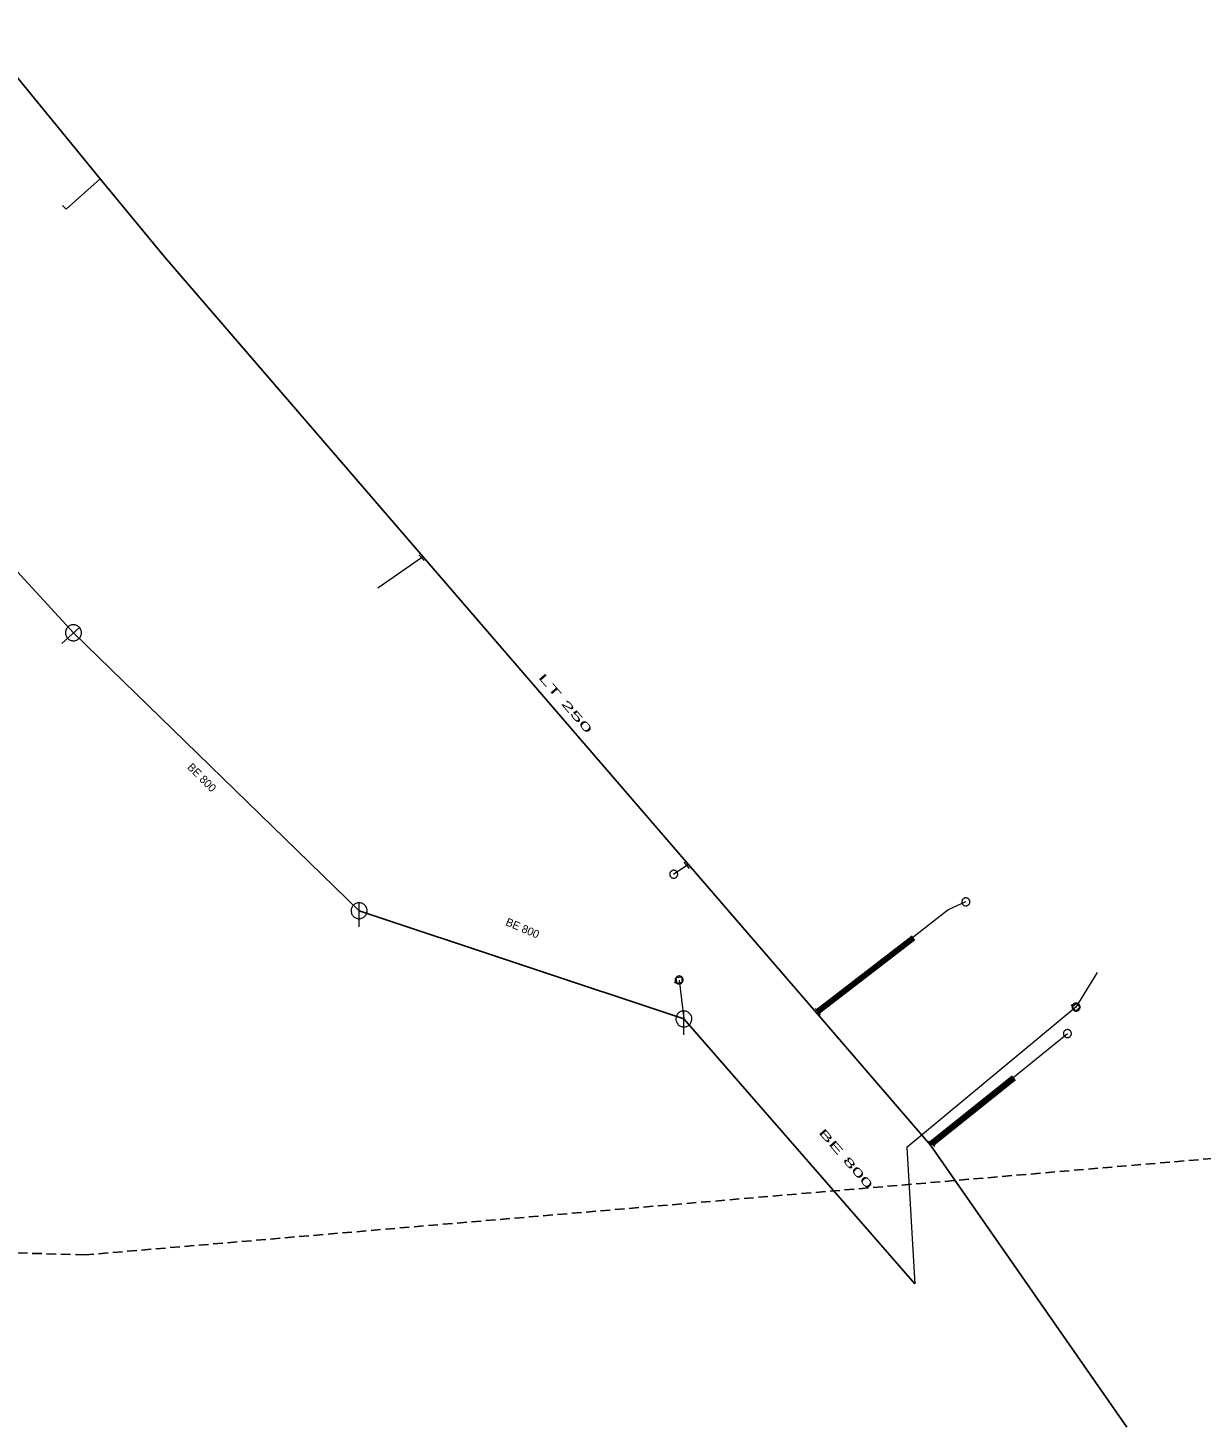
# Model space of a CAD drawing. Extents: x -807203 to -805207, y -993656 to -992505.
# Drawn here: x -805804.7 to -805658.1, y -993617.7 to -993442.8 of the extents above; entities that cross this region are included whole.
import ezdxf

# ---------------------------------------------------------------- set-up
doc = ezdxf.new("R2010")
doc.units = 0
doc.header["$LTSCALE"] = 0.4
doc.header["$PDMODE"] = 32
doc.header["$PDSIZE"] = 0.2
doc.linetypes.add('MEDIUM_DASHED', pattern=[4.5, 3, -1.5])
for name, color, linetype, lineweight in [('1', 7, 'Continuous', 13), ('11', 7, 'Continuous', 13), ('13', 7, 'Continuous', 13), ('14', 7, 'Continuous', 25), ('17', 7, 'Continuous', 25), ('22', 7, 'Continuous', 13), ('23', 7, 'Continuous', 13), ('3', 7, 'Continuous', 106), ('34', 7, 'Continuous', 13), ('63', 7, 'MEDIUM_DASHED', 25)]:
    doc.layers.add(name, color=color, linetype=linetype, lineweight=lineweight)

msp = doc.modelspace()

# ---------------------------------------------------------------- linework, layer by layer
at = {"layer": '11'}
for p, q in [((-805723.33, -993561.836), (-805722.73, -993566.67)), ((-805671.081, -993560.878), (-805673.723, -993565.2))]:
    msp.add_line(p, q, dxfattribs=at)
msp.add_lwpolyline([(-805673.723, -993565.2), (-805694.854, -993582.729), (-805693.85, -993599.78)], dxfattribs=at)
at = {"layer": '13'}
for p, q in [((-805755.528, -993509.035), (-805761.003, -993512.821)), ((-805722.359, -993547.474), (-805724.007, -993548.622)), ((-805691.744, -993582.248), (-805674.78, -993568.475)), ((-805691.895, -993582.435), (-805691.744, -993582.248))]:
    msp.add_line(p, q, dxfattribs=at)
for points in [[(-805795.712, -993461.665), (-805796.45, -993462.339), (-805799.933, -993465.458), (-805800.42, -993464.977)], [(-805705.993, -993565.763), (-805689.715, -993553.05), (-805687.47, -993552.011)]]:
    msp.add_lwpolyline(points, dxfattribs=at)
at = {"layer": '14', "lineweight": 13}
for p, q in [((-805755.36, -993508.868), (-805755.528, -993509.035)), ((-805722.18, -993547.329), (-805722.359, -993547.474)), ((-805706.16, -993565.899), (-805705.993, -993565.763))]:
    msp.add_line(p, q, dxfattribs=at)
at = {"layer": '14'}
for p, q in [((-805799.036, -993518.404), (-805763.329, -993553.149)), ((-805763.329, -993553.149), (-805722.73, -993566.67)), ((-805722.73, -993566.67), (-805693.85, -993599.78))]:
    msp.add_line(p, q, dxfattribs=at)
msp.add_lwpolyline([(-805843.754, -993470.162), (-805838.469, -993475.18), (-805826.754, -993488.287), (-805799.036, -993518.404)], dxfattribs=at)
at = {"layer": '17'}
msp.add_lwpolyline([(-805810.637, -993445.063), (-805806.327, -993448.671), (-805795.712, -993461.664), (-805787.671, -993471.416), (-805755.36, -993508.868), (-805722.18, -993547.329), (-805706.16, -993565.899), (-805691.895, -993582.435), (-805667.369, -993617.68)], dxfattribs=at)
at = {"layer": '22'}
for p, q in [((-805800.507, -993519.759), (-805798.3, -993517.726)), ((-805763.329, -993555.149), (-805763.328, -993552.149)), ((-805722.73, -993568.67), (-805722.729, -993565.67))]:
    msp.add_line(p, q, dxfattribs=at)
for points in [[(-805798.358, -993519.139), (-805798.282, -993519.061), (-805798.215, -993518.975), (-805798.157, -993518.881), (-805798.11, -993518.783), (-805798.074, -993518.679), (-805798.05, -993518.573), (-805798.038, -993518.463), (-805798.037, -993518.354), (-805798.048, -993518.245), (-805798.072, -993518.139), (-805798.106, -993518.034), (-805798.153, -993517.935), (-805798.209, -993517.841), (-805798.276, -993517.754), (-805798.352, -993517.675), (-805798.435, -993517.605), (-805798.526, -993517.543), (-805798.623, -993517.492), (-805798.726, -993517.453), (-805798.831, -993517.425), (-805798.94, -993517.409), (-805799.049, -993517.404), (-805799.159, -993517.412), (-805799.266, -993517.43), (-805799.371, -993517.462), (-805799.472, -993517.504), (-805799.568, -993517.557), (-805799.657, -993517.62), (-805799.739, -993517.693), (-805799.813, -993517.775), (-805799.877, -993517.863), (-805799.93, -993517.958), (-805799.974, -993518.058), (-805800.007, -993518.163), (-805800.027, -993518.271), (-805800.036, -993518.38), (-805800.032, -993518.49), (-805800.017, -993518.598), (-805799.99, -993518.704), (-805799.951, -993518.806), (-805799.902, -993518.904), (-805799.842, -993518.996), (-805799.772, -993519.081), (-805799.694, -993519.157), (-805799.607, -993519.224), (-805799.515, -993519.281), (-805799.416, -993519.329), (-805799.312, -993519.365), (-805799.205, -993519.389), (-805799.097, -993519.402), (-805798.987, -993519.403), (-805798.878, -993519.391), (-805798.771, -993519.369), (-805798.668, -993519.333), (-805798.568, -993519.288), (-805798.474, -993519.231), (-805798.387, -993519.164)], [(-805762.329, -993553.149), (-805762.334, -993553.04), (-805762.352, -993552.932), (-805762.382, -993552.826), (-805762.422, -993552.725), (-805762.474, -993552.628), (-805762.536, -993552.538), (-805762.608, -993552.455), (-805762.688, -993552.381), (-805762.776, -993552.315), (-805762.87, -993552.26), (-805762.97, -993552.215), (-805763.075, -993552.182), (-805763.182, -993552.16), (-805763.291, -993552.15), (-805763.401, -993552.152), (-805763.509, -993552.166), (-805763.616, -993552.191), (-805763.719, -993552.228), (-805763.817, -993552.277), (-805763.909, -993552.335), (-805763.995, -993552.404), (-805764.072, -993552.481), (-805764.141, -993552.567), (-805764.2, -993552.659), (-805764.248, -993552.757), (-805764.285, -993552.86), (-805764.311, -993552.967), (-805764.325, -993553.075), (-805764.328, -993553.185), (-805764.318, -993553.294), (-805764.297, -993553.401), (-805764.263, -993553.505), (-805764.219, -993553.605), (-805764.164, -993553.7), (-805764.098, -993553.788), (-805764.024, -993553.868), (-805763.941, -993553.94), (-805763.851, -993554.002), (-805763.755, -993554.054), (-805763.653, -993554.095), (-805763.548, -993554.125), (-805763.44, -993554.143), (-805763.33, -993554.149), (-805763.221, -993554.143), (-805763.113, -993554.125), (-805763.008, -993554.096), (-805762.906, -993554.055), (-805762.809, -993554.003), (-805762.719, -993553.941), (-805762.636, -993553.87), (-805762.561, -993553.79), (-805762.496, -993553.702), (-805762.44, -993553.608), (-805762.396, -993553.508), (-805762.362, -993553.404), (-805762.34, -993553.296), (-805762.33, -993553.187)], [(-805723.263, -993562.3), (-805723.212, -993562.291), (-805723.16, -993562.275), (-805723.112, -993562.256), (-805723.066, -993562.232), (-805723.023, -993562.203), (-805722.982, -993562.167), (-805722.947, -993562.131), (-805722.916, -993562.088), (-805722.887, -993562.045), (-805722.863, -993561.998), (-805722.845, -993561.948), (-805722.835, -993561.898), (-805722.826, -993561.846), (-805722.824, -993561.793), (-805722.83, -993561.742), (-805722.838, -993561.691), (-805722.854, -993561.639), (-805722.873, -993561.59), (-805722.897, -993561.545), (-805722.927, -993561.502), (-805722.961, -993561.462), (-805722.998, -993561.425), (-805723.04, -993561.393), (-805723.083, -993561.366), (-805723.13, -993561.343), (-805723.181, -993561.325), (-805723.231, -993561.312), (-805723.282, -993561.305), (-805723.335, -993561.305), (-805723.386, -993561.308), (-805723.438, -993561.318), (-805723.489, -993561.332), (-805723.538, -993561.351), (-805723.584, -993561.376), (-805723.626, -993561.406), (-805723.667, -993561.439), (-805723.703, -993561.477), (-805723.735, -993561.518), (-805723.763, -993561.563), (-805723.786, -993561.609), (-805723.803, -993561.66), (-805723.816, -993561.71), (-805723.824, -993561.762), (-805723.824, -993561.814), (-805723.821, -993561.865), (-805723.812, -993561.917), (-805723.796, -993561.968), (-805723.778, -993562.016), (-805723.752, -993562.062), (-805723.723, -993562.106), (-805723.689, -993562.146), (-805723.653, -993562.182), (-805723.611, -993562.213), (-805723.567, -993562.242), (-805723.519, -993562.265), (-805723.469, -993562.283), (-805723.42, -993562.295), (-805723.368, -993562.303), (-805723.314, -993562.304)], [(-805723.021, -993561.413), (-805722.932, -993562.116), (-805723.621, -993562.202), (-805723.708, -993561.499)], [(-805674.078, -993565.505), (-805674.043, -993565.544), (-805674.002, -993565.579), (-805673.96, -993565.609), (-805673.915, -993565.635), (-805673.867, -993565.655), (-805673.815, -993565.671), (-805673.765, -993565.681), (-805673.713, -993565.684), (-805673.661, -993565.686), (-805673.609, -993565.68), (-805673.556, -993565.668), (-805673.508, -993565.65), (-805673.46, -993565.63), (-805673.415, -993565.602), (-805673.375, -993565.57), (-805673.336, -993565.536), (-805673.301, -993565.495), (-805673.27, -993565.452), (-805673.244, -993565.408), (-805673.225, -993565.359), (-805673.21, -993565.309), (-805673.199, -993565.258), (-805673.194, -993565.205), (-805673.194, -993565.154), (-805673.2, -993565.102), (-805673.213, -993565.05), (-805673.229, -993565.001), (-805673.25, -993564.953), (-805673.279, -993564.909), (-805673.309, -993564.868), (-805673.345, -993564.83), (-805673.385, -993564.794), (-805673.426, -993564.762), (-805673.472, -993564.738), (-805673.52, -993564.718), (-805673.571, -993564.701), (-805673.622, -993564.692), (-805673.674, -993564.687), (-805673.726, -993564.687), (-805673.778, -993564.693), (-805673.83, -993564.706), (-805673.879, -993564.722), (-805673.927, -993564.743), (-805673.971, -993564.771), (-805674.012, -993564.801), (-805674.051, -993564.837), (-805674.086, -993564.878), (-805674.116, -993564.919), (-805674.141, -993564.966), (-805674.162, -993565.014), (-805674.178, -993565.064), (-805674.189, -993565.114), (-805674.192, -993565.166), (-805674.193, -993565.219), (-805674.187, -993565.271), (-805674.175, -993565.323), (-805674.159, -993565.371), (-805674.137, -993565.419), (-805674.109, -993565.465)], [(-805673.2, -993565.232), (-805673.745, -993565.685), (-805674.189, -993565.151), (-805673.643, -993564.699)], [(-805721.73, -993566.67), (-805721.735, -993566.561), (-805721.753, -993566.453), (-805721.783, -993566.347), (-805721.823, -993566.246), (-805721.875, -993566.149), (-805721.937, -993566.059), (-805722.009, -993565.976), (-805722.089, -993565.902), (-805722.177, -993565.836), (-805722.271, -993565.781), (-805722.371, -993565.736), (-805722.476, -993565.703), (-805722.583, -993565.681), (-805722.692, -993565.671), (-805722.802, -993565.673), (-805722.91, -993565.687), (-805723.017, -993565.712), (-805723.12, -993565.749), (-805723.218, -993565.798), (-805723.31, -993565.856), (-805723.396, -993565.925), (-805723.473, -993566.002), (-805723.542, -993566.088), (-805723.601, -993566.18), (-805723.649, -993566.278), (-805723.686, -993566.381), (-805723.712, -993566.488), (-805723.726, -993566.596), (-805723.729, -993566.706), (-805723.719, -993566.815), (-805723.698, -993566.922), (-805723.664, -993567.026), (-805723.62, -993567.126), (-805723.565, -993567.221), (-805723.499, -993567.309), (-805723.425, -993567.389), (-805723.342, -993567.461), (-805723.252, -993567.523), (-805723.156, -993567.575), (-805723.054, -993567.616), (-805722.949, -993567.646), (-805722.841, -993567.664), (-805722.731, -993567.67), (-805722.622, -993567.664), (-805722.514, -993567.646), (-805722.409, -993567.617), (-805722.307, -993567.576), (-805722.21, -993567.524), (-805722.12, -993567.462), (-805722.037, -993567.391), (-805721.962, -993567.311), (-805721.897, -993567.223), (-805721.841, -993567.129), (-805721.797, -993567.029), (-805721.763, -993566.925), (-805721.741, -993566.817), (-805721.731, -993566.708)]]:
    msp.add_lwpolyline(points, close=True, dxfattribs=at)
for p in [(-805723.742, -993562.082), (-805674.152, -993564.985)]:
    msp.add_point(p, dxfattribs=at)
at = {"layer": '23'}
for points in [[(-805723.997, -993548.09), (-805724.048, -993548.092), (-805724.1, -993548.1), (-805724.151, -993548.112), (-805724.2, -993548.132), (-805724.246, -993548.155), (-805724.29, -993548.182), (-805724.331, -993548.215), (-805724.369, -993548.252), (-805724.403, -993548.292), (-805724.431, -993548.336), (-805724.455, -993548.383), (-805724.475, -993548.43), (-805724.488, -993548.482), (-805724.497, -993548.533), (-805724.5, -993548.585), (-805724.498, -993548.638), (-805724.49, -993548.69), (-805724.477, -993548.74), (-805724.458, -993548.789), (-805724.435, -993548.835), (-805724.408, -993548.88), (-805724.375, -993548.922), (-805724.338, -993548.959), (-805724.298, -993548.991), (-805724.254, -993549.02), (-805724.208, -993549.044), (-805724.158, -993549.063), (-805724.108, -993549.077), (-805724.058, -993549.085), (-805724.005, -993549.089), (-805723.953, -993549.087), (-805723.901, -993549.08), (-805723.849, -993549.066), (-805723.801, -993549.048), (-805723.755, -993549.025), (-805723.711, -993548.997), (-805723.669, -993548.963), (-805723.632, -993548.928), (-805723.598, -993548.886)], [(-805723.598, -993548.886), (-805723.57, -993548.844), (-805723.545, -993548.798), (-805723.527, -993548.747), (-805723.513, -993548.697), (-805723.504, -993548.645), (-805723.5, -993548.593), (-805723.503, -993548.542), (-805723.511, -993548.489), (-805723.524, -993548.44), (-805723.542, -993548.39), (-805723.566, -993548.344), (-805723.594, -993548.299), (-805723.626, -993548.258), (-805723.663, -993548.221), (-805723.704, -993548.187), (-805723.747, -993548.158), (-805723.793, -993548.136), (-805723.842, -993548.116), (-805723.892, -993548.101), (-805723.945, -993548.093), (-805723.997, -993548.09), (-805724.048, -993548.092), (-805724.1, -993548.1), (-805724.151, -993548.112), (-805724.2, -993548.132), (-805724.246, -993548.155), (-805724.29, -993548.182), (-805724.331, -993548.215), (-805724.369, -993548.252), (-805724.403, -993548.292), (-805724.431, -993548.336), (-805724.455, -993548.383), (-805724.475, -993548.43), (-805724.488, -993548.482), (-805724.497, -993548.533), (-805724.5, -993548.585), (-805724.498, -993548.638), (-805724.49, -993548.69), (-805724.477, -993548.74)], [(-805724.477, -993548.74), (-805724.458, -993548.789), (-805724.435, -993548.835), (-805724.408, -993548.88)], [(-805724.408, -993548.88), (-805724.375, -993548.922), (-805724.338, -993548.959), (-805724.298, -993548.991), (-805724.254, -993549.02), (-805724.208, -993549.044), (-805724.158, -993549.063), (-805724.108, -993549.077), (-805724.058, -993549.085), (-805724.005, -993549.089), (-805723.953, -993549.087), (-805723.901, -993549.08), (-805723.849, -993549.066), (-805723.801, -993549.048), (-805723.755, -993549.025), (-805723.711, -993548.997), (-805723.669, -993548.963), (-805723.632, -993548.928), (-805723.598, -993548.886), (-805723.57, -993548.844), (-805723.545, -993548.798), (-805723.527, -993548.747), (-805723.513, -993548.697), (-805723.504, -993548.645), (-805723.5, -993548.593), (-805723.503, -993548.542), (-805723.511, -993548.489), (-805723.524, -993548.44), (-805723.542, -993548.39), (-805723.566, -993548.344), (-805723.594, -993548.299), (-805723.626, -993548.258), (-805723.663, -993548.221), (-805723.704, -993548.187), (-805723.747, -993548.158), (-805723.793, -993548.136), (-805723.842, -993548.116), (-805723.892, -993548.101), (-805723.945, -993548.093), (-805723.997, -993548.09)], [(-805687.029, -993551.826), (-805687.054, -993551.779), (-805687.084, -993551.736), (-805687.118, -993551.698), (-805687.156, -993551.661), (-805687.197, -993551.63), (-805687.243, -993551.602), (-805687.29, -993551.58), (-805687.338, -993551.563), (-805687.389, -993551.55), (-805687.441, -993551.543), (-805687.494, -993551.541), (-805687.547, -993551.546), (-805687.598, -993551.555), (-805687.647, -993551.57), (-805687.695, -993551.589), (-805687.743, -993551.615), (-805687.785, -993551.643), (-805687.826, -993551.679), (-805687.861, -993551.715), (-805687.893, -993551.756), (-805687.92, -993551.803), (-805687.943, -993551.85), (-805687.96, -993551.9), (-805687.973, -993551.95), (-805687.98, -993552.001), (-805687.98, -993552.054), (-805687.976, -993552.106), (-805687.967, -993552.157), (-805687.951, -993552.207), (-805687.932, -993552.256), (-805687.908, -993552.302), (-805687.878, -993552.345), (-805687.844, -993552.386), (-805687.806, -993552.421), (-805687.765, -993552.452), (-805687.72, -993552.479), (-805687.673, -993552.503), (-805687.623, -993552.52), (-805687.572, -993552.532)], [(-805687.826, -993551.679), (-805687.861, -993551.715), (-805687.893, -993551.756), (-805687.92, -993551.803), (-805687.943, -993551.85), (-805687.96, -993551.9), (-805687.973, -993551.95), (-805687.98, -993552.001), (-805687.98, -993552.054), (-805687.976, -993552.106), (-805687.967, -993552.157), (-805687.951, -993552.207), (-805687.932, -993552.256), (-805687.908, -993552.302), (-805687.878, -993552.345), (-805687.844, -993552.386), (-805687.806, -993552.421), (-805687.765, -993552.452), (-805687.72, -993552.479), (-805687.673, -993552.503), (-805687.623, -993552.52), (-805687.572, -993552.532), (-805687.521, -993552.54), (-805687.468, -993552.54), (-805687.416, -993552.537), (-805687.364, -993552.526), (-805687.315, -993552.511), (-805687.266, -993552.492), (-805687.221, -993552.467), (-805687.177, -993552.438), (-805687.137, -993552.404), (-805687.102, -993552.365), (-805687.069, -993552.324), (-805687.042, -993552.28), (-805687.02, -993552.232), (-805687.002, -993552.184), (-805686.99, -993552.133), (-805686.982, -993552.08), (-805686.981, -993552.028), (-805686.985, -993551.976)], [(-805687.572, -993552.532), (-805687.521, -993552.54), (-805687.468, -993552.54), (-805687.416, -993552.537), (-805687.364, -993552.526), (-805687.315, -993552.511), (-805687.266, -993552.492), (-805687.221, -993552.467), (-805687.177, -993552.438), (-805687.137, -993552.404), (-805687.102, -993552.365), (-805687.069, -993552.324), (-805687.042, -993552.28), (-805687.02, -993552.232), (-805687.002, -993552.184), (-805686.99, -993552.133), (-805686.982, -993552.08), (-805686.981, -993552.028), (-805686.985, -993551.976), (-805686.996, -993551.924), (-805687.01, -993551.875), (-805687.029, -993551.826), (-805687.054, -993551.779), (-805687.084, -993551.736), (-805687.118, -993551.698), (-805687.156, -993551.661), (-805687.197, -993551.63), (-805687.243, -993551.602), (-805687.29, -993551.58), (-805687.338, -993551.563), (-805687.389, -993551.55), (-805687.441, -993551.543), (-805687.494, -993551.541), (-805687.547, -993551.546), (-805687.598, -993551.555), (-805687.647, -993551.57), (-805687.695, -993551.589), (-805687.743, -993551.615), (-805687.785, -993551.643), (-805687.826, -993551.679)], [(-805686.985, -993551.976), (-805686.996, -993551.924), (-805687.01, -993551.875), (-805687.029, -993551.826)], [(-805674.378, -993568.217), (-805674.41, -993568.175), (-805674.447, -993568.138), (-805674.487, -993568.106), (-805674.531, -993568.076), (-805674.577, -993568.052), (-805674.627, -993568.033), (-805674.677, -993568.019), (-805674.728, -993568.011), (-805674.78, -993568.007), (-805674.832, -993568.009), (-805674.884, -993568.016), (-805674.936, -993568.03), (-805674.984, -993568.048), (-805675.03, -993568.071), (-805675.075, -993568.098), (-805675.117, -993568.132), (-805675.153, -993568.167), (-805675.187, -993568.209), (-805675.216, -993568.251), (-805675.241, -993568.297), (-805675.259, -993568.348), (-805675.273, -993568.398), (-805675.282, -993568.45), (-805675.286, -993568.502), (-805675.283, -993568.553), (-805675.275, -993568.606), (-805675.262, -993568.655), (-805675.244, -993568.705), (-805675.22, -993568.751), (-805675.193, -993568.796), (-805675.161, -993568.837), (-805675.124, -993568.875), (-805675.083, -993568.908), (-805675.04, -993568.937), (-805674.994, -993568.96), (-805674.945, -993568.979), (-805674.895, -993568.994), (-805674.843, -993569.003), (-805674.791, -993569.006)], [(-805675.187, -993568.209), (-805675.216, -993568.251), (-805675.241, -993568.297), (-805675.259, -993568.348), (-805675.273, -993568.398), (-805675.282, -993568.45), (-805675.286, -993568.502), (-805675.283, -993568.553), (-805675.275, -993568.606), (-805675.262, -993568.655), (-805675.244, -993568.705), (-805675.22, -993568.751), (-805675.193, -993568.796), (-805675.161, -993568.837), (-805675.124, -993568.875), (-805675.083, -993568.908), (-805675.04, -993568.937), (-805674.994, -993568.96), (-805674.945, -993568.979), (-805674.895, -993568.994), (-805674.843, -993569.003), (-805674.791, -993569.006), (-805674.739, -993569.005), (-805674.687, -993568.996), (-805674.636, -993568.984), (-805674.587, -993568.965), (-805674.541, -993568.941), (-805674.497, -993568.914), (-805674.456, -993568.881), (-805674.418, -993568.845), (-805674.384, -993568.804), (-805674.356, -993568.761), (-805674.331, -993568.714), (-805674.312, -993568.667), (-805674.299, -993568.615), (-805674.289, -993568.564), (-805674.286, -993568.512), (-805674.288, -993568.459), (-805674.296, -993568.407), (-805674.309, -993568.357)], [(-805674.791, -993569.006), (-805674.739, -993569.005), (-805674.687, -993568.996), (-805674.636, -993568.984), (-805674.587, -993568.965), (-805674.541, -993568.941), (-805674.497, -993568.914), (-805674.456, -993568.881), (-805674.418, -993568.845), (-805674.384, -993568.804), (-805674.356, -993568.761), (-805674.331, -993568.714), (-805674.312, -993568.667), (-805674.299, -993568.615), (-805674.289, -993568.564), (-805674.286, -993568.512), (-805674.288, -993568.459), (-805674.296, -993568.407), (-805674.309, -993568.357), (-805674.328, -993568.308), (-805674.35, -993568.262), (-805674.378, -993568.217), (-805674.41, -993568.175), (-805674.447, -993568.138), (-805674.487, -993568.106), (-805674.531, -993568.076), (-805674.577, -993568.052), (-805674.627, -993568.033), (-805674.677, -993568.019), (-805674.728, -993568.011), (-805674.78, -993568.007), (-805674.832, -993568.009), (-805674.884, -993568.016), (-805674.936, -993568.03), (-805674.984, -993568.048), (-805675.03, -993568.071), (-805675.075, -993568.098), (-805675.117, -993568.132), (-805675.153, -993568.167), (-805675.187, -993568.209)], [(-805674.309, -993568.357), (-805674.328, -993568.308), (-805674.35, -993568.262), (-805674.378, -993568.217)]]:
    msp.add_lwpolyline(points, dxfattribs=at)
at = {"layer": '3'}
for p, q in [((-805705.993, -993565.763), (-805694.004, -993556.552)), ((-805691.744, -993582.248), (-805681.499, -993574.037))]:
    msp.add_line(p, q, dxfattribs=at)
at = {"layer": '3', "lineweight": 100}
for p, q in [((-805705.993, -993565.763), (-805694.004, -993556.552)), ((-805691.744, -993582.248), (-805681.499, -993574.037))]:
    msp.add_line(p, q, dxfattribs=at)
at = {"layer": '34'}
for p, q in [((-805755.174, -993509.388), (-805755.88, -993508.68)), ((-805722.043, -993547.862), (-805722.673, -993547.085)), ((-805706.308, -993565.374), (-805705.678, -993566.151)), ((-805692.133, -993581.934), (-805691.355, -993582.562))]:
    msp.add_line(p, q, dxfattribs=at)
at = {"layer": '63'}
msp.add_lwpolyline([(-807189.02, -992945.815), (-806576.348, -992585.749), (-806576.348, -992585.749), (-805244.939, -992598.309), (-805244.939, -992598.309), (-805207.257, -992947.211), (-805207.257, -992947.211), (-805210.049, -993545.926), (-805210.049, -993545.926), (-805797.599, -993596.168), (-805797.599, -993596.168), (-807062.019, -993558.487), (-807062.019, -993558.487)], close=True, dxfattribs=at)

# ---------------------------------------------------------------- texts
at = {"layer": '1'}
for s, width, p in [('LT 250', 2.25, (-805740.996, -993524.01)), ('BE 800', 2.15, (-805705.959, -993580.896))]:
    msp.add_text(s, height=1, rotation=311, dxfattribs=dict(at, width=width)).set_placement(p)
for rotation, p in [(315, (-805784.895, -993535.292)), (337, (-805745.104, -993554.925))]:
    msp.add_text('BE 800', height=1, rotation=rotation, dxfattribs=at).set_placement(p)

doc.saveas('drawing.dxf')
